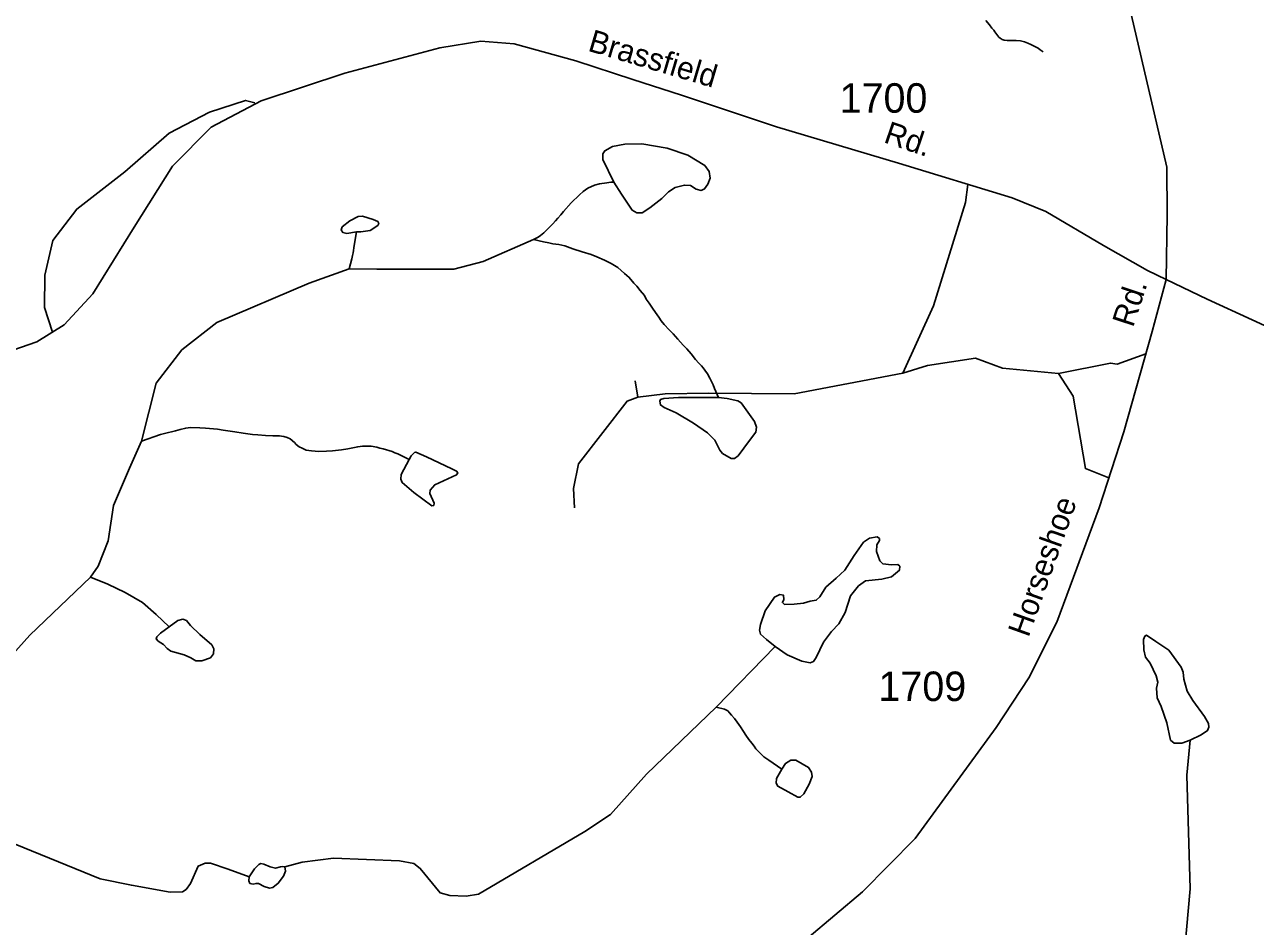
# Model space of a CAD drawing. Extents: x 2056842 to 2160602, y 826753 to 1016856.
# Drawn here: x 2120707 to 2125925, y 858312 to 862136 of the extents above; entities that cross this region are included whole.
import ezdxf

# ---------------------------------------------------------------- set-up
doc = ezdxf.new("R2010")
doc.units = 0
for name, color, linetype in [('Exist Hydrographic Creek Single Shore', 7, 'Continuous'), ('Exist Hydrographic Misc Water Feature', 7, 'Continuous'), ('Exist Road Non-System Type 51', 7, 'Continuous'), ('Exist Road Primary NC Attributed', 7, 'Continuous'), ('Exist Road Secondary Type 51 Attributed', 7, 'Continuous'), ('Exist Road Secondary Type 51 Label', 7, 'Continuous'), ('Exist Road Secondary Type 51 Number Label', 7, 'Continuous')]:
    doc.layers.add(name, color=color, linetype=linetype)

msp = doc.modelspace()

# ---------------------------------------------------------------- linework, layer by layer
at = {"layer": 'Exist Hydrographic Creek Single Shore'}
msp.add_lwpolyline([(2125024.7, 862020.9), (2125013, 862029.6), (2125003.7, 862035.5), (2124995.1, 862039.6), (2124986.5, 862044.9), (2124973.4, 862051.9), (2124960.5, 862057), (2124945.5, 862062.9), (2124928.7, 862066.7), (2124910.7, 862068.6), (2124904.3, 862068.8), (2124888.5, 862068.3), (2124882.6, 862068.4), (2124872.3, 862068.4), (2124860.2, 862069.7), (2124850.6, 862073.2), (2124843, 862078), (2124837.4, 862082.9), (2124828.6, 862094), (2124820.4, 862105.8), (2124816.3, 862111.8), (2124807.7, 862121.5), (2124797.7, 862134.8), (2124782.1, 862153.5)], dxfattribs=at)
at = {"layer": 'Exist Hydrographic Misc Water Feature'}
for points in [[(2123205.2, 861468.3), (2123159, 861564.5), (2123157.8, 861588.4), (2123166.5, 861600.9), (2123199.2, 861618.5), (2123251.9, 861628.6), (2123323.5, 861629.8), (2123431.5, 861612.2), (2123519.4, 861582.1), (2123591, 861538.1), (2123608.5, 861513), (2123613.6, 861485.3), (2123603.5, 861459), (2123589.7, 861440.1), (2123574.6, 861432.6), (2123554.6, 861437.6), (2123529.4, 861453.9), (2123504.3, 861455.2), (2123465.4, 861445.1), (2123436.5, 861427.5), (2123408.9, 861398.7), (2123357.4, 861358.4), (2123324.8, 861338.3), (2123302.2, 861338.3), (2123282.1, 861349.7), (2123236.9, 861416.2), (2123205.2, 861468.3)], [(2123205.2, 861468.3), (2123192.7, 861467.4), (2123174.7, 861465.2), (2123144.5, 861461.2), (2123122.6, 861454.5), (2123094.7, 861442.5), (2123075, 861428), (2123059, 861413.8), (2123023.6, 861379.7), (2122991.6, 861343.6), (2122979.9, 861329.2), (2122967.8, 861315.5), (2122958.1, 861303.2), (2122946.3, 861291.2), (2122930.5, 861275.3), (2122920.2, 861264.8), (2122908.9, 861252.7), (2122894.8, 861242.2), (2122884.5, 861234.4), (2122864, 861225)], [(2122114.2, 861257), (2122072.9, 861250.4), (2122056.5, 861254.2), (2122049, 861265.5), (2122052.8, 861278), (2122085.4, 861303.2), (2122120.6, 861322), (2122139.4, 861323.3), (2122184.6, 861309.4), (2122204.7, 861300.7), (2122208.5, 861293.1), (2122204.7, 861284.3), (2122172.1, 861263), (2122131.9, 861256.7), (2122114.2, 861257)], [(2120205.7, 858970), (2120322.9, 859000.6), (2120356.4, 859024), (2120392.8, 859093.1), (2120413.7, 859175.9), (2120463.1, 859250.2), (2120728.9, 859546.7), (2120986.7, 859793), (2121019.8, 859839.3), (2121060.9, 859946.7), (2121084.7, 860097), (2121152.5, 860255.3), (2121202.7, 860369.6), (2121265.7, 860615.1), (2121373.8, 860757.3), (2121522.8, 860872.3), (2121913.4, 861039.3), (2122082.9, 861099.6), (2122200.9, 861098.4), (2122526.2, 861098.4), (2122650.5, 861131), (2122864, 861225)], [(2122114.2, 861257), (2122104.1, 861199.7), (2122099.8, 861167.9), (2122097.1, 861157.3), (2122093.9, 861143.2), (2122082.9, 861099.6)], [(2123648.7, 860554.3), (2123631.9, 860592.9), (2123626, 860608.8), (2123619.4, 860622.9), (2123611.6, 860637), (2123601.6, 860655.2), (2123591.3, 860671), (2123583.8, 860681), (2123577.4, 860688.5), (2123565.3, 860700.5), (2123551, 860716.1), (2123532.9, 860740.3), (2123514.5, 860760.5), (2123498.5, 860776.4), (2123476.3, 860801.6), (2123456.2, 860824.1), (2123440, 860841.6), (2123418.1, 860864.7), (2123406, 860879.2), (2123395.3, 860895), (2123381.4, 860915), (2123369.5, 860933.4), (2123355.3, 860955.1), (2123342.8, 860972.3), (2123334.6, 860986.5), (2123317, 861007.9), (2123302.4, 861026.3), (2123290.3, 861039.9), (2123270.2, 861064), (2123249.9, 861080.1), (2123222.3, 861105.5), (2123193.8, 861123.1), (2123165.5, 861136.7), (2123133.3, 861150.6), (2123109.5, 861160.6), (2123070.9, 861172.1), (2123031.1, 861185.4), (2122997.1, 861197.5), (2122971.3, 861203.1), (2122947.1, 861206.8), (2122929, 861210.7), (2122906.9, 861215.3), (2122864, 861225)], [(2123648.7, 860554.3), (2123479.2, 860554.3), (2123416.4, 860550.6), (2123402.6, 860545.5), (2123400.1, 860539.3), (2123402.6, 860522.9), (2123418.9, 860511.6), (2123469.2, 860489), (2123543.3, 860446.3), (2123602.3, 860404.8), (2123633.7, 860373.4), (2123653.8, 860330.7), (2123666.3, 860316.9), (2123702.7, 860295.5), (2123716.5, 860295.5), (2123731.6, 860306.8), (2123780.6, 860372.2), (2123806.9, 860407.3), (2123809.5, 860428.7), (2123801.9, 860452.6), (2123744.2, 860531.7), (2123730.3, 860540.5), (2123685.1, 860550.6), (2123648.7, 860554.3)], [(2122337.8, 860291.8), (2122289.3, 860315.1), (2122277.2, 860319.4), (2122264.9, 860325.2), (2122226.9, 860336.7), (2122213, 860340), (2122201.1, 860344.6), (2122177.1, 860348.3), (2122158.6, 860347.8), (2122139.2, 860347.6), (2122119.3, 860345.7), (2122099, 860341.8), (2122077, 860337.4), (2122050.8, 860332.9), (2122013.1, 860328.9), (2121987.2, 860326.7), (2121955.2, 860325.9), (2121923.5, 860328.3), (2121901.5, 860332), (2121883.3, 860339.7), (2121871, 860345.5), (2121859.1, 860355.9), (2121851.1, 860363.2), (2121832.8, 860379.4), (2121820.7, 860385.2), (2121806.8, 860388.9), (2121786.7, 860392.4), (2121759, 860392.2), (2121728.2, 860393.5), (2121696.3, 860396), (2121672.9, 860398.2), (2121633.7, 860403), (2121598.4, 860408.7), (2121548.4, 860416.3), (2121524.8, 860419.9), (2121474.6, 860424.3), (2121450.6, 860425.8), (2121410.4, 860427.5), (2121390.5, 860425.2), (2121366.5, 860419.1), (2121346.8, 860413.2), (2121300.9, 860402.6), (2121282.7, 860398.1), (2121202.7, 860369.6)], [(2122337.8, 860291.8), (2122303.9, 860227.7), (2122302.7, 860208.8), (2122307.7, 860193.8), (2122356.6, 860152.3), (2122433.2, 860095.8), (2122442, 860097), (2122443.3, 860107.1), (2122425.7, 860147.3), (2122427, 860162.3), (2122445.8, 860185), (2122538.7, 860226.4), (2122543.7, 860235.2), (2122538.7, 860242.8), (2122518.6, 860251.5), (2122410.6, 860303.1), (2122365.4, 860323.2), (2122360.4, 860321.9), (2122345.3, 860306.8), (2122337.8, 860291.8)], [(2123888.6, 859499), (2123940, 859463.8), (2124001.6, 859436.1), (2124036.7, 859429.9), (2124051.8, 859434.9), (2124063.1, 859452.5), (2124093.2, 859517.8), (2124127.1, 859561.8), (2124158.5, 859594.4), (2124186.2, 859643.4), (2124208.8, 859713.8), (2124242.7, 859756.5), (2124271.5, 859776.6), (2124340.6, 859784.2), (2124382, 859794.2), (2124415.9, 859821.9), (2124417.2, 859839.4), (2124408.4, 859847), (2124382, 859845.7), (2124345.6, 859849.5), (2124333.1, 859862.1), (2124318, 859902.3), (2124320.5, 859929.9), (2124331.8, 859948.7), (2124330.6, 859956.3), (2124321.8, 859963.8), (2124289.1, 859957.5), (2124264, 859941.2), (2124223.8, 859884.7), (2124184.9, 859823.1), (2124147.2, 859789.2), (2124103.3, 859750.2), (2124078.2, 859710), (2124063.1, 859695), (2124036.7, 859691.2), (2124009.1, 859682.4), (2123970.2, 859678.6), (2123928.7, 859677.4), (2123920, 859684.9), (2123926.2, 859697.5), (2123925, 859716.3), (2123908.7, 859718.8), (2123886, 859707.5), (2123845.9, 859649.7), (2123827, 859591.9), (2123822, 859568.1), (2123827, 859550.5), (2123852.1, 859527.9), (2123888.6, 859499)], [(2121320.7, 859581.9), (2121265.5, 859634.6), (2121206.5, 859684.9), (2121133.6, 859727.6), (2121059.5, 859762.8), (2120986.7, 859793)], [(2121320.7, 859581.9), (2121283, 859555.5), (2121268, 859539.2), (2121265.5, 859531.6), (2121273, 859521.6), (2121295.6, 859507.8), (2121311.9, 859490.2), (2121327, 859478.9), (2121383.5, 859463.8), (2121412.4, 859450), (2121433.7, 859437.4), (2121458.8, 859437.4), (2121495.3, 859450), (2121507.8, 859467.5), (2121509.1, 859488.9), (2121501.5, 859505.2), (2121450.1, 859549.2), (2121409.9, 859588.2), (2121393.5, 859609.5), (2121378.5, 859614.5), (2121357.1, 859608.3), (2121320.7, 859581.9)], [(2125647.8, 859102), (2125694.3, 859124.6), (2125721.9, 859142.2), (2125726.9, 859156), (2125725.7, 859172.4), (2125709.3, 859202.5), (2125659.1, 859269.1), (2125635.3, 859309.3), (2125621.4, 859359.6), (2125618.9, 859389.7), (2125610.1, 859411.1), (2125557.4, 859482.7), (2125502.1, 859520.4), (2125463.2, 859546.8), (2125455.7, 859543), (2125450.7, 859527.9), (2125451.9, 859485.2), (2125458.2, 859453.8), (2125478.3, 859427.4), (2125504.7, 859374.7), (2125510.9, 859347), (2125505.9, 859321.9), (2125508.4, 859281.7), (2125524.8, 859244), (2125548.6, 859174.9), (2125564.9, 859102), (2125580, 859089.5), (2125612.7, 859089.5), (2125647.8, 859102)], [(2121810.4, 858564.2), (2121883.3, 858584.3), (2122016.8, 858601.5), (2122296.4, 858589.3), (2122357.8, 858578.1), (2122384.3, 858557.9), (2122468.4, 858453.6), (2122509.8, 858442.3), (2122578.9, 858439.8), (2122631.6, 858448.6), (2123081.8, 858714.1), (2123190.4, 858786.6), (2123343.6, 858957.4), (2123638.3, 859241.7), (2123888.6, 859499)], [(2123917.4, 858978.8), (2123862, 859016.6), (2123841.5, 859031.2), (2123827.8, 859042.9), (2123807.5, 859064.7), (2123799.3, 859076.5), (2123789.4, 859088.9), (2123776.7, 859104.6), (2123765.2, 859122.2), (2123754.8, 859138), (2123742.7, 859157.7), (2123728.1, 859177.7), (2123716.4, 859193.7), (2123704.3, 859207.7), (2123696.1, 859217.9), (2123688.1, 859225.6), (2123674, 859233), (2123638.3, 859241.7)], [(2122064.1, 853954.5), (2122098, 853999.7), (2122452.1, 854360.3), (2122616.6, 854557.5), (2122788.6, 854757.3), (2123180.7, 855198.1), (2123388.8, 855407.2), (2123603.7, 855766.8), (2123776.7, 856166.8), (2124083.7, 856462.4), (2124706.7, 856954.8), (2125500.9, 857660.9), (2125552.4, 857727.5), (2125578.7, 857776.5), (2125626.7, 857933.2), (2125625.7, 858218.7), (2125647.8, 858471.3), (2125634, 858952.5), (2125647.8, 859102)], [(2123917.4, 858978.8), (2123894.8, 858938.6), (2123893.6, 858919.7), (2123899.9, 858905.9), (2123943.8, 858882.1), (2123985.2, 858859.4), (2123995.3, 858859.4), (2124010.4, 858873.3), (2124033, 858914.7), (2124045.5, 858947.4), (2124043, 858966.2), (2124030.5, 858986.3), (2123976.5, 859016.5), (2123955.1, 859016.5), (2123932.5, 859002.7), (2123917.4, 858978.8)], [(2120205.7, 858970), (2120557.9, 858703.7), (2121026.9, 858513.9), (2121160, 858486.3), (2121324.5, 858457.4), (2121376, 858458.6), (2121392.3, 858468.7), (2121411.1, 858493.8), (2121442.5, 858566.7), (2121472.7, 858579.3), (2121495.3, 858580.5), (2121570.6, 858554.1), (2121659.7, 858522.7)], [(2121659.7, 858522.7), (2121657.2, 858505.1), (2121662.3, 858493.8), (2121676.1, 858491.3), (2121688.6, 858493.8), (2121698.7, 858493.8), (2121722.5, 858481.3), (2121745.1, 858473.7), (2121760.2, 858476.2), (2121782.8, 858495.1), (2121804.2, 858525.2), (2121812.9, 858546.6), (2121810.4, 858564.2)], [(2121659.7, 858522.7), (2121682.4, 858555.4), (2121699.9, 858574.2), (2121708.7, 858578), (2121721.3, 858575.5), (2121747.6, 858564.2), (2121771.5, 858559.2), (2121791.6, 858564.2), (2121800.4, 858565.4), (2121810.4, 858564.2)]]:
    msp.add_lwpolyline(points, dxfattribs=at)
at = {"layer": 'Exist Road Non-System Type 51'}
msp.add_line((2123306.7, 860555.8), (2123295.3, 860625.5), dxfattribs=at)
for points in [[(2120825.2, 860832.2), (2120791.5, 860936.2), (2120793.5, 861073.4), (2120826.8, 861220.9), (2120928.6, 861354), (2121132.1, 861511.9), (2121320.1, 861675.1), (2121490.4, 861764.4), (2121644.1, 861814.3), (2121683.9, 861803.8)], [(2124706.2, 861458.1), (2124695.2, 861382), (2124560.2, 860943.5), (2124430.4, 860657.7)], [(2124430.4, 860657.7), (2124534.2, 860690.9), (2124737.8, 860722.1), (2124852, 860678.5), (2125089.8, 860656.6)], [(2125089.8, 860656.6), (2125310, 860700.3), (2125339.1, 860696.1), (2125460, 860739.3)], [(2124430.4, 860657.7), (2123969.3, 860570.4), (2123607.9, 860572.5), (2123423, 860570.4), (2123306.7, 860555.8)], [(2125089.8, 860656.6), (2125152.2, 860561), (2125204.1, 860253.4), (2125303.3, 860214.4)], [(2123306.7, 860555.8), (2123261, 860539.2), (2123055.4, 860273.2), (2123034.6, 860169.2), (2123038.8, 860086.1)]]:
    msp.add_lwpolyline(points, dxfattribs=at)
at = {"layer": 'Exist Road Primary NC Attributed'}
for points in [[(2125545.9, 861054.7), (2125550.7, 861329.4), (2125548.8, 861531), (2125388.2, 862222.2), (2125214.4, 862983.8), (2125185.8, 863151.1), (2125191.5, 863289.9), (2125249.5, 863737.7), (2125312.2, 864241.6)], [(2126641.5, 860591.5), (2126370.7, 860674.4), (2126101.8, 860797), (2125719.8, 860971.9), (2125545.9, 861054.7)]]:
    msp.add_lwpolyline(points, dxfattribs=at)
at = {"layer": 'Exist Road Secondary Type 51 Attributed'}
for points in [[(2125545.9, 861054.7), (2125467.6, 861092.7), (2125281.3, 861199.2), (2125036.2, 861343.7), (2124893.7, 861400.7), (2124412, 861548.1), (2123895.1, 861702.1), (2123491.3, 861836.2), (2123286.1, 861902.7), (2123044.7, 861982.6), (2122782.5, 862054.9), (2122641.9, 862066.3), (2122468, 862036.8), (2122065.1, 861930.3), (2121709.8, 861812.4), (2121497.9, 861701.2), (2121334.5, 861535.7), (2121171.1, 861277.1), (2120997.2, 860994.7), (2120875.6, 860863.5), (2120759.6, 860791.3), (2120558.2, 860720.9)], [(2123907.9, 858160.9), (2124258.5, 858458.5), (2124482.7, 858684.8), (2124825.7, 859155.5), (2124964.5, 859366.5), (2125082.3, 859602.3), (2125261.9, 860086.3), (2125366.4, 860409.5), (2125487, 860834.5), (2125545.9, 861054.7)]]:
    msp.add_lwpolyline(points, dxfattribs=at)

# ---------------------------------------------------------------- texts
at = {"layer": 'Exist Road Secondary Type 51 Label'}
for s, rotation, p in [('Brassfield', 343.5365, (2123091, 862025.7)), ('Rd.', 341.2497, (2124344.7, 861637.8)), ('Rd.', 71.7683, (2125405.9, 860848.4)), ('Horseshoe', 70.3826, (2124962.9, 859534.1))]:
    msp.add_text(s, height=95, rotation=rotation, dxfattribs=at).set_placement(p)
at = {"layer": 'Exist Road Secondary Type 51 Number Label'}
for s, p in [('1700', (2124162.4, 861762.3)), ('1709', (2124327, 859267.5))]:
    msp.add_text(s, height=125, dxfattribs=at).set_placement(p)

doc.saveas('drawing.dxf')
